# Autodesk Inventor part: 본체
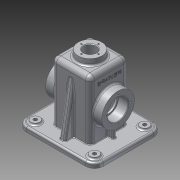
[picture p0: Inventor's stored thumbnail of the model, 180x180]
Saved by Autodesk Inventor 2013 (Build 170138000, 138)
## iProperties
Created: 2016-06
Part Number: 본체
Material: 알루미늄 6061
Document SubType Name: Modeling
Designer: home
Density: 2.71 g/cm^3
Mass: 806.269 g
Surface Area: 909.624 cm^2
Volume: 297.516 cm^3
Author: home
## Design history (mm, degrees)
sketch "스케치1"
  geometry: L1 (32.5, 32.5)-(-32.5, 32.5); L2 (-32.5, 32.5)-(-32.5, -32.5); L3 (-32.5, -32.5)-(32.5, -32.5); L4 (32.5, -32.5)-(32.5, 32.5); L5 (32.5, 32.5)-(-32.5, -32.5); L6 (-32.5, 32.5)-(32.5, -32.5); 1 further point
  constraints: 12 end point, 2 midpoint, 2 parallel, 2 perpendicular, 1 horizontal
  dimensions: "d0" = 65 distance between parallel lines of L2 L4
extrude "돌출1" new body sketch "스케치1" distance "d2" = 110; taper "d3" = 0 deg
sketch "스케치2"
  geometry: L1 (65, 57.5)-(-65, 57.5); L2 (-65, 57.5)-(-65, -57.5); L3 (-65, -57.5)-(65, -57.5); L4 (65, -57.5)-(65, 57.5); L5 (65, 57.5)-(-65, -57.5); L6 (-65, 57.5)-(65, -57.5); 1 further point
  constraints: 12 end point, 2 midpoint, 2 parallel, 1 horizontal, 1 perpendicular
  dimensions: "d4" = 130 distance between parallel lines of L2 L4; "d6" = 115 distance between parallel lines of L1 L3
extrude "돌출2" join sketch "스케치2" distance "d7" = 10; taper "d8" = 0 deg
fillet "모깎기1" dims "d9" = 15
sketch "스케치3"
  geometry: L1 (-50, 57.5)-(50, 57.5) reference; L2 (-65, -42.5)-(-65, 42.5) reference; L3 (50, -57.5)-(-50, -57.5) reference; L4 (65, 42.5)-(65, -42.5) reference; L5 (60, 42.5)-(60, -42.5); L6 (50, -52.5)-(-50, -52.5); L7 (-60, -42.5)-(-60, 42.5); L8 (-50, 52.5)-(50, 52.5); A1 r 15 centre (50, 42.5) between (65, 42.5) and (50, 57.5) reference; A2 r 15 centre (-50, 42.5) between (-50, 57.5) and (-65, 42.5) reference; A3 r 15 centre (-50, -42.5) between (-65, -42.5) and (-50, -57.5) reference; A4 r 15 centre (50, -42.5) between (50, -57.5) and (65, -42.5) reference; A5 r 10 centre (50, 42.5) between (60, 42.5) and (50, 52.5); A6 r 10 centre (50, -42.5) between (50, -52.5) and (60, -42.5); A7 r 10 centre (-50, -42.5) between (-60, -42.5) and (-50, -52.5); A8 r 10 centre (-50, 42.5) between (-50, 52.5) and (-60, 42.5); 1 further point
  constraints: 8 end point, 8 point on circle, 4 centre point, 7 other
  dimensions: "d10" = 5 distance between parallel lines of L8 L1
extrude "돌출3" cut sketch "스케치3" distance "d11" = 2; taper "d12" = 0 deg
feature "쉘1" dims "d13" = 10, "d14" = 5
sketch "스케치4"
  geometry: L1 (0, -100)-(65, -100) reference; L2 (65, -100)-(65, 0) reference; L3 (0, 0)-(65, 0) reference; L4 (0, -100)-(0, 0) reference; L5 (75, -110)-(-10, -110) reference; C1 r 27.5 at (32.5, -55); 2 further points
  constraints: 1 centre point, 1 midpoint, 1 vertical alignment
  dimensions: "d15" = 55 distance of point (32.5, -110) C1.centre; "d17" = 55 diameter of C1
extrude "돌출4" join sketch "스케치4" distance "d18" = 15; taper "d19" = 0 deg
sketch "스케치5"
  geometry: C1 r 27.5 at (0, 0) reference; C2 r 17.5 at (0, 0); 1 further point
  constraints: 1 centre point, 1 coincident
  dimensions: "d20" = 35 diameter of C2
extrude "돌출5" cut sketch "스케치5" distance "d23" = 17; taper "d24" = 0 deg
sketch "스케치6"
  geometry: C1 r 17.5 at (55, 0) reference; C2 r 15 at (55, 0); 1 further point
  constraints: 1 centre point, 1 coincident
  dimensions: "d25" = 30 diameter of C2
extrude "돌출6" cut sketch "스케치6" stored distance "d27" = 17; taper "d28" = 0 deg
sketch "스케치7"
  geometry: L1 (10, -32.5)-(10, -57.5) reference; L2 (10, -57.5)-(2, -57.5) reference; L3 (2, -57.5)-(2, -52.5) reference; L4 (2, -52.5)-(0, -52.5) reference; L5 (0, -52.5)-(0, -27.5) reference; L6 (0, -27.5)-(105, -27.5) reference; L7 (105, -27.5)-(105, 27.5) reference; L8 (105, 27.5)-(0, 27.5) reference; L9 (0, 27.5)-(0, 52.5) reference; L10 (0, 52.5)-(2, 52.5) reference; L11 (2, 52.5)-(2, 57.5) reference; L12 (2, 57.5)-(10, 57.5) reference; L13 (10, 57.5)-(10, 32.5) reference; L14 (10, 32.5)-(110, 32.5) reference; L15 (110, 32.5)-(110, -32.5) reference; L16 (110, -32.5)-(10, -32.5) reference; L17 (10, 47.5)-(95.069, 32.5); 1 further point
  constraints: 2 end point, 2 point on line
  dimensions: "d29" = 10 distance from line of L17.start L12; "d30" = 10 deg angle of L12 L17
feature "리브1" sketch "스케치7" dims "d31" = 1, "d32" = 10, "d33" = 0, "d34" = 0, "d35" = 1, "d36" = 1
sketch "스케치8"
  geometry: L1 (-32.5, 27.5)-(-47.5, 27.5) reference; L2 (-47.5, 27.5)-(-47.5, 37.5) reference; L3 (-47.5, 37.5)-(-30.5, 37.5) reference; L4 (-30.5, 37.5)-(-30.5, 40) reference; L5 (-30.5, 40)-(-27.5, 40) reference; L6 (-27.5, 40)-(-27.5, 0) reference; L7 (-27.5, 0)-(-60, 0) reference; L8 (-60, 0)-(-60, 2) reference; L9 (-60, 2)-(-65, 2) reference; L10 (-65, 2)-(-65, 10) reference; L11 (-65, 10)-(-32.5, 10) reference; L12 (-32.5, 10)-(-32.5, 27.5) reference; L13 (47.5, 27.5)-(32.5, 27.5) reference; L14 (47.5, 37.5)-(47.5, 27.5) reference; L15 (30.5, 37.5)-(47.5, 37.5) reference; L16 (47.5, 72.5)-(30.5, 72.5) reference; L17 (47.5, 82.5)-(47.5, 72.5) reference; L18 (32.5, 82.5)-(47.5, 82.5) reference; L19 (32.5, 27.5)-(32.5, 10) reference; L20 (32.5, 10)-(65, 10) reference; L21 (65, 10)-(65, 2) reference; L22 (65, 2)-(60, 2) reference; L23 (60, 2)-(60, 0) reference; L24 (60, 0)-(27.5, 0) reference; L25 (27.5, 0)-(27.5, 40) reference; L26 (27.5, 105)-(-27.5, 105) reference; L27 (-27.5, 105)-(-27.5, 70) reference; L28 (-27.5, 70)-(-30.5, 70) reference; L29 (-30.5, 70)-(-30.5, 72.5) reference; L30 (-30.5, 72.5)-(-47.5, 72.5) reference; L31 (-47.5, 72.5)-(-47.5, 82.5) reference; L32 (-47.5, 82.5)-(-32.5, 82.5) reference; L33 (-32.5, 82.5)-(-32.5, 110) reference; L34 (-32.5, 110)-(32.5, 110) reference; L35 (32.5, 110)-(32.5, 82.5) reference; L36 (42.5, 82.5)-(42.5, 10); L37 (27.5, 40)-(30.5, 40) reference; L38 (30.5, 40)-(30.5, 37.5) reference; L39 (30.5, 72.5)-(30.5, 70) reference; L40 (30.5, 70)-(27.5, 70) reference; L41 (27.5, 70)-(27.5, 105) reference; 1 further point
  constraints: 2 end point, 2 point on line, 1 perpendicular
  dimensions: "d37" = 15 distance between parallel lines of L36 L25
feature "리브2" sketch "스케치8" dims "d38" = 1, "d39" = 6, "d40" = 0, "d41" = 0, "d42" = 1, "d43" = 1
node "작업 평면1"
sketch "스케치9"
  geometry: C1 r 20 at (0, 0); 1 further point
  constraints: 1 centre point, 1 coincident
  dimensions: "d45" = 40 diameter of C1
extrude "돌출7" join sketch "스케치9" distance "d47" = 10; taper "d48" = 5 deg
hole "구멍1" diameter "d51" = 21; stored, may be unused: countersink angle "d55" = 90 deg, drill point angle "d57" = 118 deg; dims "d52" = 6, "d53" = 4, "d54" = 2, "d56" = 8, "d58" = 10, "d59" = 10
fillet "모깎기2" dims "d60" = 8
fillet "모깎기3" dims "d61" = 8
fillet "모깎기4" dims "d62" = 3
fillet "모깎기5" dims "d63" = 3
fillet "모깎기6" dims "d64" = 3
fillet "모깎기9" dims "d67" = 3
fillet "모깎기10" dims "d68" = 3
fillet "모깎기11" dims "d69" = 3
fillet "모깎기12" dims "d70" = 3
fillet "모깎기13" dims "d71" = 3
fillet "모깎기15" dims "d73" = 3
fillet "모깎기16" dims "d74" = 3
fillet "모깎기17" dims "d75" = 3
chamfer "모따기1" distance "d76" = 1; stored, may be unused: second distance "d77" = 2, angle "d78" = 45 deg
sketch "스케치10"
  geometry: C1 r 27.5 at (0, 0) reference; 2 further points
  constraints: 1 vertical alignment
  dimensions: "d79" = 21 distance of C1.centre point (0, 21)
hole "구멍2" sketch "스케치10" at (0, 21) diameter "d80" = 3.242; stored, may be unused: countersink angle "d84" = 90 deg, drill point angle "d86" = 118 deg; dims "d81" = 8, "d82" = 4, "d83" = 2, "d85" = 10
sketch "스케치11"
  geometry: C1 r 27.5 at (0, 0) reference; 2 further points
  constraints: 1 vertical alignment
  dimensions: "d90" = 21 distance of C1.centre point (0, 21)
hole "구멍3" sketch "스케치11" at (0, 21) diameter "d91" = 3.242; stored, may be unused: countersink angle "d95" = 90 deg, drill point angle "d97" = 118 deg; dims "d92" = 8, "d93" = 4, "d94" = 2, "d96" = 10
sketch "스케치12"
  geometry: C1 r 20 at (0, 0) reference; 1 further point
  constraints: 1 vertical alignment
  dimensions: "d101" = 14.5 distance of C1.centre point (0, 14.5)
hole "구멍4" sketch "스케치12" at (0, 14.5) diameter "d102" = 2.459; stored, may be unused: countersink angle "d106" = 90 deg, drill point angle "d108" = 118 deg; dims "d103" = 7, "d104" = 4, "d105" = 2, "d107" = 9
sketch "스케치13"
  geometry: L1 (-8, 0)-(-8, -92) reference; L2 (4.5, 18)-(44.5, 18) reference; 3 further points
  constraints: 1 other
  dimensions: "d112" = 32.5 distance from line of point (24.5, -8) L1; "d113" = 26 distance from line of point (24.5, -8) L2
feature "엠보싱1" sketch "스케치13" dims "d114" = 0.5, "d115" = 0
sketch "스케치14"
  geometry: C1 r 7.5 at (-50, -42.5); C2 r 7.5 at (-50, 42.5); C3 r 7.5 at (50, 42.5); C4 r 7.5 at (50, -42.5); A1 r 12 centre (-50, -42.5) between (-62, -42.5) and (-50, -54.5) reference; A2 r 12 centre (50, -42.5) between (50, -54.5) and (62, -42.5) reference; A3 r 12 centre (50, 42.5) between (62, 42.5) and (50, 54.5) reference; A4 r 12 centre (-50, 42.5) between (-50, 54.5) and (-62, 42.5) reference; 1 further point
  constraints: 4 centre point, 4 coincident, 3 equal radius
  dimensions: "d116" = 15 diameter of C2
extrude "돌출8" join sketch "스케치14" distance "d118" = 3; taper "d119" = 0 deg
hole "구멍5" diameter "d122" = 6; stored, may be unused: countersink angle "d126" = 90 deg, drill point angle "d128" = 0 deg; dims "d120" = 10, "d121" = 10, "d123" = 7, "d124" = 4, "d125" = 2, "d127" = 9
hole "구멍6" diameter "d131" = 6; stored, may be unused: countersink angle "d135" = 90 deg, drill point angle "d137" = 0 deg; dims "d129" = 10, "d130" = 10, "d132" = 7, "d133" = 4, "d134" = 2, "d136" = 9
hole "구멍7" diameter "d140" = 6; stored, may be unused: countersink angle "d144" = 90 deg, drill point angle "d146" = 0 deg; dims "d138" = 10, "d139" = 10, "d141" = 7, "d142" = 4, "d143" = 2, "d145" = 9
hole "구멍8" diameter "d149" = 6; stored, may be unused: countersink angle "d153" = 90 deg, drill point angle "d155" = 0 deg; dims "d147" = 10, "d148" = 10, "d150" = 7, "d151" = 4, "d152" = 2, "d154" = 9
fillet "모깎기18" dims "d156" = 3
fillet "모깎기19" dims "d157" = 0.3
sketch "스케치15"
  geometry: L1 (110, -23.624)-(110, -24.5) reference; L2 (102, -32.5)-(10, -32.5) reference; L3 (10, -32.5)-(10, -54.5) reference; L4 (7, -57.5)-(2, -57.5) reference; L5 (2, -57.5)-(2, -52.5) reference; L6 (2, -52.5)-(0, -52.5) reference; L7 (0, -52.5)-(0, -27.5) reference; L8 (0, -27.5)-(102, -27.5) reference; L9 (105, -24.5)-(105, -10.5) reference; L10 (105, -10.5)-(119, -10.5) reference; L11 (119, -10.5)-(120, -11.5) reference; L12 (120, -11.5)-(120, -13.271) reference; L13 (120, -13.271)-(111, -13.271) reference; L14 (111, -13.271)-(110.261, -14.5) reference; L15 (110.261, -14.5)-(111, -15.73) reference; L16 (111, -15.73)-(120, -15.73) reference; L17 (120, -15.73)-(120, -20) reference; L18 (120, -20)-(112.739, -20.635) reference; L19 (95.332, 32.5)-(102, 32.5) reference; L20 (110, 24.5)-(110, 23.624) reference; L21 (112.739, 20.635)-(120, 20) reference; L22 (120, 20)-(120, 15.73) reference; L23 (120, 15.73)-(111, 15.73) reference; L24 (111, 15.73)-(110.261, 14.5) reference; L25 (110.261, 14.5)-(111, 13.271) reference; L26 (111, 13.271)-(120, 13.271) reference; L27 (120, 13.271)-(120, 11.5) reference; L28 (120, 11.5)-(119, 10.5) reference; L29 (119, 10.5)-(105, 10.5) reference; L30 (105, 10.5)-(105, 24.5) reference; L31 (102, 27.5)-(0, 27.5) reference; L32 (0, 27.5)-(0, 52.5) reference; L33 (0, 52.5)-(2, 52.5) reference; L34 (2, 52.5)-(2, 57.5) reference; L35 (2, 57.5)-(7, 57.5) reference; L36 (10, 54.5)-(10, 47.5) reference; L37 (10, 47.5)-(94.811, 32.546) reference; L38 (95.069, -32.5)-(10, -47.5); A1 r 3 centre (113, -23.624) between (112.739, -20.635) and (110, -23.624) reference; A2 r 8 centre (102, -24.5) between (102, -32.5) and (110, -24.5) reference; A3 r 3 centre (7, -54.5) between (7, -57.5) and (10, -54.5) reference; A4 r 3 centre (102, -24.5) between (102, -27.5) and (105, -24.5) reference; A5 r 3 centre (95.332, 35.5) between (94.811, 32.546) and (95.332, 32.5) reference; A6 r 8 centre (102, 24.5) between (110, 24.5) and (102, 32.5) reference; A7 r 3 centre (113, 23.624) between (110, 23.624) and (112.739, 20.635) reference; A8 r 3 centre (102, 24.5) between (105, 24.5) and (102, 27.5) reference; A9 r 3 centre (7, 54.5) between (10, 54.5) and (7, 57.5) reference; 1 further point
  constraints: 2 end point, 2 point on line
  dimensions: "d158" = 10 distance from line of L4 L38.end; "d159" = 10 deg angle of L4 L38
feature "리브3" sketch "스케치15" dims "d160" = 1, "d161" = 10, "d162" = 0, "d163" = 0, "d164" = 1, "d165" = 1
fillet "모깎기20" dims "d166" = 3
fillet "모깎기21" dims "d167" = 3
fillet "모깎기22" dims "d168" = 1
node "솔리드1"
mirror "대칭1"
mirror "대칭3"
pattern_circular "원형 패턴1" dims angle "d88" = 360 deg
pattern_circular "원형 패턴2" dims angle "d99" = 360 deg
pattern_circular "원형 패턴3" dims angle "d110" = 360 deg
node "투영된 루프1"
node "절단 모서리 투영1"
node "절단 모서리 투영2"
node "절단 모서리 투영3"
